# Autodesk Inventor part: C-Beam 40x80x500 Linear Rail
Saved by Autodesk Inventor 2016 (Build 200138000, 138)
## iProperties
Created: 2015-11
Part Number: C-Beam 40x80x500 Linear Rail
Material: Generic
Document SubType Name: Modeling
Designer: John
Density: 1 g/cm^3
Appearance: Default
Author: John
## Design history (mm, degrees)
feature "SOLID1"
body "Solid1"
